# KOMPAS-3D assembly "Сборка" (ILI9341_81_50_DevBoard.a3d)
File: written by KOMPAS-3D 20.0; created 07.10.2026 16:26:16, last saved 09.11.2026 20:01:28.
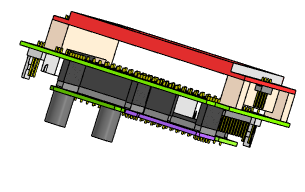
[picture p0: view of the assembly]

Document properties: Полное имя файла: D:\RicWork\Project-EPS32\box_compas\сборки компонентов\ILI9341_81_50_DevBoard.a3d

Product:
- Part/product: Сборка
    Масса: 0.290133
  - Component [assembly]: Сборка  | Масса: 0.132179; source file: макетка+модули.a3d
  - Component [assembly]: Сборка  | Масса: 0.157954; source file: ..\монитор\ILI9341_81_50 asm+.a3d

Referenced files in D:\RicWork\Project-EPS32\box_compas\монитор\: ILI9341_81_50 asm+.a3d
Referenced files in D:\RicWork\Project-EPS32\box_compas\сборки компонентов\: макетка+модули.a3d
